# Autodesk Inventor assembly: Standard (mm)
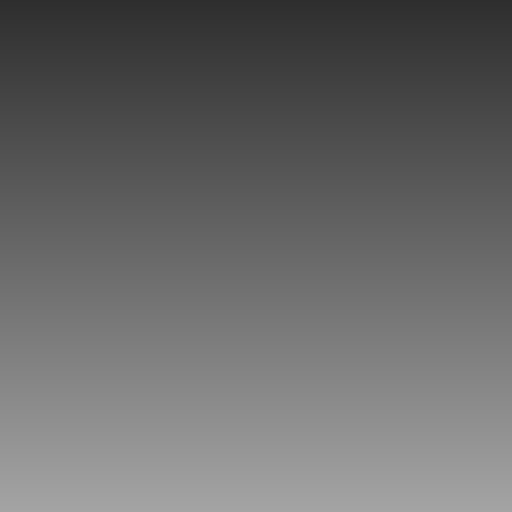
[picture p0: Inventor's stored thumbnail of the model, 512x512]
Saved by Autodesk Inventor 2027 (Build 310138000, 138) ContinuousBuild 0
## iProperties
Created: 2002-07
Part Number: Standard (mm)
Document SubType Name: Assembly
Control State: 0
Master: False
Checked Out: False
Shininess: 64.0
Length Units: 11269
Angle Units: 11279
Time Units: 11290
Mass Units: 11283
Length Display Precision: 3
Angle Display Precision: 2
Compacted: True
Density: 0.0
Volumn: 0.0
Area: 0.0
PropertySet Name: Model Information
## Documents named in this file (1)
- D:\AUTOBUILD\inventor\Application\App\Templates\en-US\Metric\Standard (mm).iam
